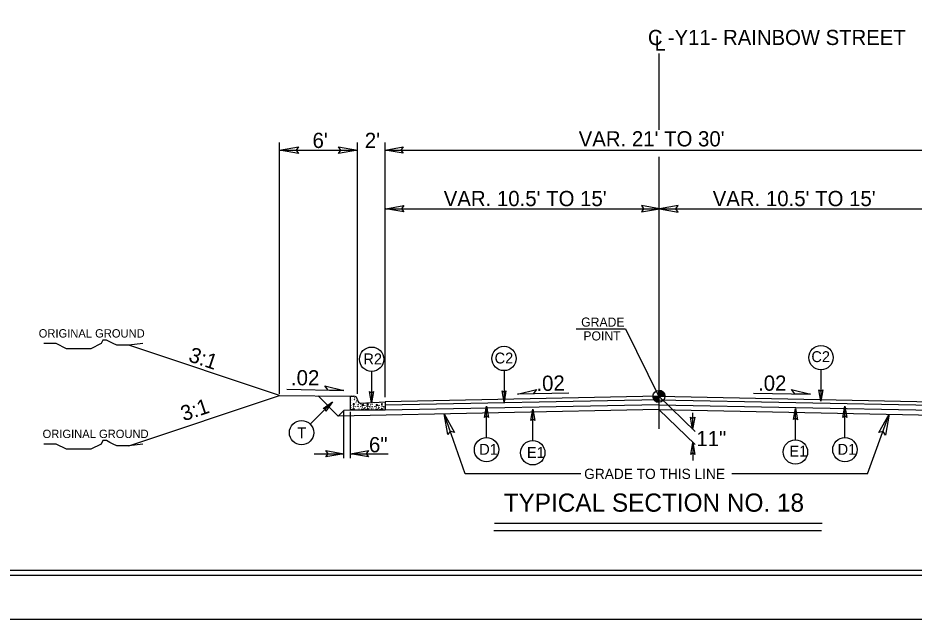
# Model space of a CAD drawing. Extents: x 957297 to 961629, y 830661 to 840840.
# Drawn here: x 959109.5 to 959568.3, y 831969.8 to 832277.6 of the extents above; entities that cross this region are included whole.
import ezdxf

# ---------------------------------------------------------------- set-up
doc = ezdxf.new("R2010")
doc.units = 0
for name, color, linetype in [('Default', 7, 'Continuous'), ('Old_Level_1', 7, 'Continuous'), ('Old_Level_11', 7, 'Continuous'), ('Old_Level_21', 7, 'Continuous'), ('Old_Level_3', 7, 'Continuous'), ('Prop Dimension Text', 7, 'Continuous'), ('Sheet Plot Border Inside CELL', 7, 'Continuous'), ('Sheet Plot Border Outside CELL', 7, 'Continuous'), ('Sheet Typical CELL', 7, 'Continuous'), ('Typical ID Circle CELL', 7, 'Continuous'), ('Typical Terminator CELL', 7, 'Continuous'), ('Typical Text Grade Point CELL', 7, 'Continuous'), ('Typical Text ID Circle CELL', 7, 'Continuous')]:
    doc.layers.add(name, color=color, linetype=linetype)

msp = doc.modelspace()

# ---------------------------------------------------------------- linework, layer by layer
at = {"layer": 'Default'}
for p, q in [((959437.72, 832259.33), (959437.72, 832220.36)), ((959437.72, 832206.44), (959437.72, 832067.17))]:
    msp.add_line(p, q, dxfattribs=at)
at = {"layer": 'Old_Level_1'}
for p, q in [((959243.49, 832085.16), (959243.49, 832213.72)), ((959283.31, 832085.16), (959283.31, 832213.72)), ((959297.55, 832083.47), (959297.55, 832213.72)), ((959243.49, 832209.87), (959283.31, 832209.87)), ((959297.55, 832209.87), (959577.94, 832209.87)), ((959297.81, 832179.86), (959437.97, 832179.86)), ((959437.97, 832179.86), (959578.19, 832179.86)), ((959243.49, 832084.22), (959166.3, 832109.95)), ((959166.3, 832058.49), (959243.49, 832084.22)), ((959243.49, 832084.22), (959279.75, 832083.85)), ((959247.13, 832087.44), (959276.35, 832086.85)), ((959273.48, 832073.69), (959263.16, 832084.02)), ((959437.72, 832083.84), (959297.55, 832081.01)), ((959391.59, 832085.45), (959365.21, 832084.92)), ((959434.66, 832083.83), (959437.72, 832083.83)), ((959437.72, 832083.83), (959437.72, 832086.9)), ((959437.72, 832083.84), (959577.94, 832081.01)), ((959437.72, 832083.84), (959456.19, 832065.91)), ((959440.78, 832083.83), (959437.72, 832083.83)), ((959437.72, 832080.78), (959437.72, 832083.83)), ((959437.72, 832083.83), (959437.72, 832080.78)), ((959486.07, 832085.54), (959515.29, 832084.95)), ((959437.72, 832082.12), (959297.55, 832079.28)), ((959437.72, 832079.56), (959297.55, 832076.73)), ((959437.72, 832082.12), (959577.94, 832079.28)), ((959437.72, 832079.56), (959577.94, 832076.73)), ((959437.72, 832077.02), (959273.48, 832073.69)), ((959276.45, 832076.66), (959273.48, 832073.69)), ((959279.75, 832076.73), (959276.45, 832076.66)), ((959276.45, 832052.17), (959276.45, 832076.22)), ((959279.75, 832052.17), (959279.75, 832075.93)), ((959338.54, 832044.15), (959327.78, 832074.79)), ((959437.72, 832077.02), (959456.19, 832059.09)), ((959437.72, 832077.02), (959602.01, 832073.69)), ((959454.98, 832075.45), (959454.98, 832067.09)), ((959544.48, 832044.08), (959555.64, 832074.63)), ((959455.04, 832060.19), (959455.05, 832050.97)), ((959261.26, 832054.47), (959276.45, 832054.47)), ((959279.75, 832054.47), (959299.02, 832054.47)), ((959397.67, 832044.15), (959338.54, 832044.15)), ((959544.48, 832044.08), (959475.06, 832044.08)), ((959520.94, 832014.9), (959353.24, 832014.9)), ((959521.22, 832018.71), (959353.52, 832018.71))]:
    msp.add_line(p, q, dxfattribs=at)
for points in [[(959434.68, 832083.83), (959434.68, 832083.51)], [(959434.74, 832083.83), (959434.74, 832083.15)], [(959434.8, 832083.83), (959434.8, 832082.93)], [(959434.86, 832083.83), (959434.86, 832082.74)], [(959434.93, 832083.83), (959434.93, 832082.6)], [(959434.99, 832083.83), (959434.99, 832082.47)], [(959435.05, 832083.83), (959435.05, 832082.36)], [(959435.11, 832083.83), (959435.11, 832082.24)], [(959435.17, 832083.83), (959435.17, 832082.16)], [(959435.23, 832083.83), (959435.23, 832082.07)], [(959435.3, 832083.83), (959435.3, 832081.98)], [(959435.36, 832083.83), (959435.36, 832081.91)], [(959435.42, 832083.83), (959435.42, 832081.84)], [(959435.47, 832083.83), (959435.47, 832081.76)], [(959435.53, 832083.83), (959435.53, 832081.7)], [(959435.6, 832083.83), (959435.6, 832081.64)], [(959435.66, 832083.83), (959435.66, 832081.59)], [(959435.72, 832083.83), (959435.72, 832081.53)], [(959435.78, 832083.83), (959435.78, 832081.48)], [(959435.85, 832083.83), (959435.85, 832081.42)], [(959435.9, 832083.83), (959435.9, 832081.38)], [(959435.96, 832083.83), (959435.96, 832081.34)], [(959436.02, 832083.83), (959436.02, 832081.3)], [(959436.09, 832083.83), (959436.09, 832081.25)], [(959436.15, 832083.83), (959436.15, 832081.21)], [(959436.21, 832083.83), (959436.21, 832081.17)], [(959436.28, 832083.83), (959436.28, 832081.14)], [(959436.33, 832083.83), (959436.33, 832081.13)], [(959436.39, 832083.83), (959436.39, 832081.09)], [(959436.46, 832083.83), (959436.46, 832081.05)], [(959436.52, 832083.83), (959436.52, 832081.03)], [(959436.58, 832083.83), (959436.58, 832081)], [(959436.64, 832083.83), (959436.64, 832080.98)], [(959436.7, 832083.83), (959436.7, 832080.96)], [(959436.75, 832083.83), (959436.75, 832080.94)], [(959436.82, 832083.83), (959436.82, 832080.92)], [(959436.88, 832083.83), (959436.88, 832080.9)], [(959436.94, 832083.83), (959436.94, 832080.88)], [(959437, 832083.83), (959437, 832080.88)], [(959437.07, 832083.83), (959437.07, 832080.85)], [(959437.13, 832083.83), (959437.13, 832080.84)], [(959437.19, 832083.83), (959437.19, 832080.84)], [(959437.25, 832083.83), (959437.25, 832080.82)], [(959437.31, 832083.83), (959437.31, 832080.8)], [(959437.38, 832083.83), (959437.38, 832080.8)], [(959437.44, 832083.83), (959437.44, 832080.8)], [(959437.5, 832083.83), (959437.5, 832080.78)], [(959437.56, 832083.83), (959437.56, 832080.78)], [(959437.61, 832083.83), (959437.61, 832080.78)], [(959437.67, 832083.83), (959437.67, 832080.78), (959437.67, 832080.78)], [(959437.76, 832086.9), (959437.76, 832086.9), (959437.76, 832083.83)], [(959437.81, 832086.9), (959437.81, 832083.83)], [(959437.87, 832086.89), (959437.87, 832083.83)], [(959437.94, 832086.88), (959437.94, 832083.83)], [(959438, 832086.88), (959438, 832083.83)], [(959438.06, 832086.88), (959438.06, 832083.83)], [(959438.12, 832086.87), (959438.12, 832083.83)], [(959438.18, 832086.87), (959438.18, 832083.83)], [(959438.23, 832086.84), (959438.23, 832083.83)], [(959438.3, 832086.84), (959438.3, 832083.83)], [(959438.36, 832086.83), (959438.36, 832083.83)], [(959438.42, 832086.81), (959438.42, 832083.83)], [(959438.49, 832086.79), (959438.49, 832083.83)], [(959438.55, 832086.78), (959438.55, 832083.83)], [(959438.61, 832086.76), (959438.61, 832083.83)], [(959438.67, 832086.74), (959438.67, 832083.83)], [(959438.74, 832086.72), (959438.73, 832083.83)], [(959438.79, 832086.7), (959438.79, 832083.83)], [(959438.85, 832086.69), (959438.85, 832083.83)], [(959438.92, 832086.66), (959438.92, 832083.83)], [(959438.98, 832086.63), (959438.98, 832083.83)], [(959439.04, 832086.59), (959439.04, 832083.83)], [(959439.09, 832086.57), (959439.09, 832083.83)], [(959439.15, 832086.55), (959439.15, 832083.83)], [(959439.21, 832086.51), (959439.21, 832083.83)], [(959439.28, 832086.47), (959439.28, 832083.83)], [(959439.34, 832086.43), (959439.34, 832083.83)], [(959439.4, 832086.39), (959439.4, 832083.83)], [(959439.47, 832086.34), (959439.47, 832083.83)], [(959439.52, 832086.31), (959439.52, 832083.83)], [(959439.59, 832086.26), (959439.59, 832083.83)], [(959439.65, 832086.21), (959439.65, 832083.83)], [(959439.71, 832086.17), (959439.71, 832083.83)], [(959439.77, 832086.11), (959439.77, 832083.83)], [(959439.83, 832086.05), (959439.83, 832083.83)], [(959439.9, 832085.99), (959439.9, 832083.83)], [(959439.95, 832085.93), (959439.95, 832083.83)], [(959440.01, 832085.87), (959440.01, 832083.83)], [(959440.07, 832085.8), (959440.07, 832083.83)], [(959440.13, 832085.71), (959440.13, 832083.83)], [(959440.2, 832085.63), (959440.2, 832083.83)], [(959440.26, 832085.55), (959440.26, 832083.83)], [(959440.32, 832085.46), (959440.32, 832083.83)], [(959440.38, 832085.35), (959440.38, 832083.83)], [(959440.44, 832085.24), (959440.44, 832083.83)], [(959440.5, 832085.1), (959440.5, 832083.83)], [(959440.57, 832084.95), (959440.57, 832083.83)], [(959440.63, 832084.79), (959440.63, 832083.83)], [(959440.69, 832084.58), (959440.69, 832083.83)], [(959440.75, 832084.28), (959440.75, 832083.83)]]:
    msp.add_lwpolyline(points, dxfattribs=at)
msp.add_circle((959437.72, 832083.84), 3.06, dxfattribs=at)
for start, end in [(179.9905, 269.9905), (359.9905, 89.9905)]:
    msp.add_arc((959437.72, 832083.84), 3.06, start, end, dxfattribs=at)
at = {"layer": 'Old_Level_11'}
for p, q in [((959268.34, 832087.01), (959266.61, 832089.27)), ((959266.61, 832089.27), (959276.35, 832086.85)), ((959276.35, 832086.85), (959268.34, 832087.01)), ((959365.21, 832084.92), (959374.96, 832087.34)), ((959373.23, 832085.08), (959365.21, 832084.92)), ((959374.96, 832087.34), (959373.23, 832085.08)), ((959507.28, 832085.11), (959505.55, 832087.37)), ((959505.55, 832087.37), (959515.29, 832084.95)), ((959515.29, 832084.95), (959507.28, 832085.11))]:
    msp.add_line(p, q, dxfattribs=at)
for points in [[(959253.1, 832208.22), (959243.49, 832209.87), (959253.15, 832211.58), (959251.93, 832209.87)], [(959273.71, 832211.53), (959283.31, 832209.87), (959273.65, 832208.16), (959274.88, 832209.87)], [(959447.58, 832181.51), (959437.97, 832179.86), (959447.64, 832178.14), (959446.41, 832179.86)], [(959329.55, 832064.21), (959327.78, 832074.79), (959333.06, 832065.38), (959330.85, 832066.04)], [(959550.3, 832065.33), (959555.64, 832074.63), (959553.76, 832064.01), (959552.46, 832065.91)]]:
    msp.add_lwpolyline(points, close=True, dxfattribs=at)
at = {"layer": 'Old_Level_21'}
for points in [[(959173.4, 832110.83), (959166.3, 832109.95), (959164.53, 832109.95), (959161.87, 832109.95), (959160.09, 832109.95), (959158.32, 832110.83), (959156.54, 832111.73), (959154.77, 832112.61), (959153, 832112.61), (959152.1, 832110.83), (959150.34, 832109.95), (959148.56, 832109.05), (959146.79, 832108.18), (959145.02, 832108.18), (959143.25, 832108.18), (959141.47, 832108.18), (959139.7, 832108.18), (959137.92, 832108.18), (959136.15, 832108.18), (959134.38, 832108.18), (959132.61, 832109.05), (959130.84, 832109.95), (959129.07, 832110.83), (959126.39, 832110.83), (959124.62, 832110.83), (959122.85, 832110.83)], [(959173.4, 832059.37), (959166.3, 832058.49), (959164.53, 832058.49), (959161.87, 832058.49), (959160.09, 832058.49), (959158.32, 832059.37), (959156.54, 832060.26), (959154.77, 832061.14), (959153, 832061.14), (959152.1, 832059.37), (959150.34, 832058.49), (959148.56, 832057.59), (959146.79, 832056.72), (959145.02, 832056.72), (959143.25, 832056.72), (959141.47, 832056.72), (959139.7, 832056.72), (959137.92, 832056.72), (959136.15, 832056.72), (959134.38, 832056.72), (959132.61, 832057.59), (959130.84, 832058.49), (959129.07, 832059.37), (959126.39, 832059.37), (959124.62, 832059.37), (959122.85, 832059.37)]]:
    msp.add_lwpolyline(points, dxfattribs=at)
at = {"layer": 'Old_Level_3'}
for p, q in [((959279.75, 832080.29), (959279.75, 832083.55)), ((959280.06, 832083.85), (959281.54, 832083.85)), ((959279.75, 832076.73), (959279.75, 832080.29)), ((959281.12, 832080.04), (959281.12, 832079.42)), ((959281.75, 832080.01), (959281.12, 832080.04)), ((959281.12, 832079.42), (959281.75, 832080.01)), ((959283.46, 832081.66), (959283.34, 832081.5)), ((959283.34, 832081.5), (959283.5, 832081.54)), ((959285.16, 832080.39), (959297.55, 832081.01)), ((959285.16, 832080.39), (959285.16, 832080.39)), ((959285.65, 832079.61), (959285.75, 832079.09)), ((959286.54, 832079.36), (959285.65, 832079.61)), ((959285.75, 832079.09), (959286.54, 832079.36)), ((959288.35, 832080.04), (959288.35, 832079.42)), ((959288.98, 832080.01), (959288.35, 832080.04)), ((959288.35, 832079.42), (959288.98, 832080.01)), ((959292.88, 832079.61), (959292.98, 832079.09)), ((959293.77, 832079.36), (959292.88, 832079.61)), ((959292.98, 832079.09), (959293.77, 832079.36)), ((959295.58, 832080.04), (959295.58, 832079.42)), ((959296.2, 832080.01), (959295.58, 832080.04)), ((959295.58, 832079.42), (959296.2, 832080.01)), ((959297.55, 832081.01), (959297.55, 832076.73)), ((959297.55, 832076.73), (959279.75, 832076.73)), ((959281.03, 832077.14), (959281.53, 832077.84)), ((959281.71, 832077.18), (959281.03, 832077.14)), ((959281.53, 832077.84), (959281.71, 832077.18)), ((959285.45, 832076.85), (959285.81, 832077.51)), ((959286.41, 832077.08), (959285.45, 832076.85)), ((959285.81, 832077.51), (959286.41, 832077.08)), ((959288.26, 832077.14), (959288.75, 832077.84)), ((959288.94, 832077.18), (959288.26, 832077.14)), ((959288.75, 832077.84), (959288.94, 832077.18)), ((959292.68, 832076.85), (959293.04, 832077.51)), ((959293.64, 832077.08), (959292.68, 832076.85)), ((959293.04, 832077.51), (959293.64, 832077.08)), ((959295.48, 832077.14), (959295.98, 832077.84)), ((959296.17, 832077.18), (959295.48, 832077.14)), ((959295.98, 832077.84), (959296.17, 832077.18))]:
    msp.add_line(p, q, dxfattribs=at)
for centre in [(959281.72, 832083.08), (959279.81, 832081.99), (959279.91, 832079.22), (959280.5, 832080.51), (959280.63, 832081.9), (959280.66, 832078.79), (959280.8, 832082.69), (959281.49, 832078.89), (959281.89, 832082.09), (959282.35, 832078.52), (959282.58, 832080.71), (959282.88, 832079.52), (959282.91, 832082.95), (959282.94, 832081.56), (959283.54, 832078.43), (959283.64, 832078.72), (959283.67, 832079.58), (959283.77, 832080.67), (959284.83, 832080.01), (959285.12, 832078.56), (959286.38, 832079.85), (959287.14, 832079.22), (959287.89, 832078.79), (959288.72, 832078.89), (959289.58, 832078.52), (959290.11, 832079.52), (959290.77, 832078.43), (959290.86, 832078.72), (959290.9, 832079.58), (959292.05, 832080.01), (959292.35, 832078.56), (959293.61, 832079.85), (959294.37, 832079.22), (959294.95, 832080.51), (959295.12, 832078.79), (959295.94, 832078.89), (959296.8, 832078.52), (959297.03, 832080.71), (959297.33, 832079.52), (959279.95, 832076.88), (959280.04, 832078.07), (959280.5, 832077.14), (959281.23, 832078.3), (959282.51, 832077.94), (959283.37, 832077.44), (959284.1, 832077.61), (959285.82, 832078.27), (959286.84, 832077.71), (959286.94, 832078.27), (959287.17, 832076.88), (959287.26, 832078.07), (959287.73, 832077.14), (959288.45, 832078.3), (959289.74, 832077.94), (959290.6, 832077.44), (959291.33, 832077.61), (959293.05, 832078.27), (959294.07, 832077.71), (959294.17, 832078.27), (959294.4, 832076.88), (959294.49, 832078.07), (959294.95, 832077.14), (959295.68, 832078.3), (959296.97, 832077.94)]:
    msp.add_circle(centre, 0.0464, dxfattribs=at)
for centre, radius, start, end in [((959280.06, 832083.55), 0.309, 90, 180), ((959279.95, 832083.78), 0.0464, 259.6531, 10.3469), ((959281.54, 832082.08), 1.78, 1.0734, 90), ((959285.07, 832082.14), 1.76, 181.0734, 272.8624), ((959287.73, 832080.51), 0.0464, 167.7795, 17.938), ((959291, 832080.67), 0.0464, 169.8374, 15.8801), ((959279.71, 832078.27), 0.0464, 330.4173, 29.5827)]:
    msp.add_arc(centre, radius, start, end, dxfattribs=at)
at = {"layer": 'Sheet Plot Border Inside CELL'}
msp.add_lwpolyline([(960390.3, 833047.34), (958723.8, 833047.34), (958723.8, 831992.24), (960390.3, 831992.24)], close=True, dxfattribs=at)
at = {"layer": 'Sheet Plot Border Outside CELL'}
msp.add_lwpolyline([(960394.8, 833069.79), (958710.8, 833069.79), (958710.8, 831969.79), (960394.8, 831969.79)], close=True, dxfattribs=at)
at = {"layer": 'Sheet Typical CELL'}
msp.add_lwpolyline([(960377.8, 833044.79), (958877.8, 833044.79), (958877.8, 831994.79), (960377.8, 831994.79)], close=True, dxfattribs=at)
at = {"layer": 'Typical ID Circle CELL'}
for p, q in [((959358.39, 832096.98), (959358.39, 832080.9)), ((959520.68, 832097.44), (959520.68, 832081.35)), ((959290.59, 832096.61), (959290.59, 832080.52)), ((959259.12, 832069.61), (959270.49, 832080.98)), ((959349.43, 832062.76), (959349.43, 832078.85)), ((959532.93, 832062.76), (959532.93, 832078.85)), ((959373.11, 832061.17), (959373.11, 832077.26)), ((959507.59, 832061.57), (959507.59, 832077.66))]:
    msp.add_line(p, q, dxfattribs=at)
for centre in [(959290.59, 832102.84), (959358.39, 832103.21), (959520.68, 832103.67), (959254.72, 832065.2), (959349.43, 832056.54), (959373.11, 832054.95), (959507.59, 832055.35), (959532.93, 832056.54)]:
    msp.add_circle(centre, 6.23, dxfattribs=at)
at = {"layer": 'Typical Terminator CELL'}
for points in [[(959306.72, 832208.28), (959297.5, 832209.87), (959306.77, 832211.51), (959305.59, 832209.87)], [(959307.03, 832178.27), (959297.81, 832179.86), (959307.08, 832181.5), (959305.9, 832179.86)], [(959428.75, 832178.27), (959437.97, 832179.86), (959428.7, 832181.5), (959429.88, 832179.86)], [(959291.58, 832086.29), (959290.59, 832080.52), (959289.56, 832086.32), (959290.59, 832085.58)], [(959359.39, 832086.66), (959358.39, 832080.9), (959357.37, 832086.69), (959358.39, 832085.96)], [(959521.67, 832087.12), (959520.68, 832081.35), (959519.66, 832087.15), (959520.68, 832086.41)], [(959265.72, 832077.61), (959270.49, 832080.98), (959267.12, 832076.16), (959266.92, 832077.4)], [(959348.44, 832073.08), (959349.43, 832078.85), (959350.45, 832073.05), (959349.43, 832073.79)], [(959531.94, 832073.08), (959532.93, 832078.85), (959533.95, 832073.05), (959532.93, 832073.79)], [(959372.12, 832071.49), (959373.11, 832077.26), (959374.13, 832071.46), (959373.11, 832072.2)], [(959506.6, 832071.9), (959507.59, 832077.66), (959508.62, 832071.86), (959507.59, 832072.6)], [(959456.02, 832073.16), (959454.98, 832067.09), (959453.9, 832073.19), (959454.98, 832072.41)], [(959454, 832054.13), (959455.04, 832060.19), (959456.12, 832054.09), (959455.04, 832054.87)], [(959267.23, 832056.06), (959276.45, 832054.47), (959267.18, 832052.83), (959268.36, 832054.47)], [(959288.97, 832052.88), (959279.75, 832054.47), (959289.03, 832056.11), (959287.85, 832054.47)]]:
    msp.add_lwpolyline(points, close=True, dxfattribs=at)
at = {"layer": 'Typical Text Grade Point CELL'}
for p, q in [((959395.28, 832118.39), (959420.61, 832118.39)), ((959420.61, 832118.39), (959437.72, 832083.83))]:
    msp.add_line(p, q, dxfattribs=at)

# ---------------------------------------------------------------- texts
at = {"layer": 'Old_Level_1'}
for s, height, p in [("VAR. 21' TO 30'", 7.8009, (959396.61, 832211.8)), ("VAR. 10.5' TO 15'", 7.8009, (959327.52, 832181.21)), ("VAR. 10.5' TO 15'", 7.8009, (959465.25, 832181.21)), ('GRADE TO THIS LINE', 5.2473, (959399.43, 832041.52)), ('TYPICAL SECTION NO. 18', 9.3239, (959358.19, 832024.75))]:
    msp.add_text(s, height=height, dxfattribs=at).set_placement(p)
at = {"layer": 'Old_Level_11'}
for s, height, p in [('GRADE', 4.671, (959397.89, 832119.51)), ('POINT', 4.671, (959399.02, 832112.44)), ('11"', 7.801, (959456.86, 832058.32))]:
    msp.add_text(s, height=height, dxfattribs=at).set_placement(p)
at = {"layer": 'Old_Level_21'}
for p in [(959120.14, 832113.94), (959122.13, 832062.48)]:
    msp.add_text('ORIGINAL GROUND', height=4.2722, dxfattribs=at).set_placement(p)
at = {"layer": 'Old_Level_3'}
for s, p in [("6'", (959260.34, 832210.99)), ("2'", (959287.11, 832210.99))]:
    msp.add_text(s, height=7.801, dxfattribs=at).set_placement(p)
for s, rotation, p in [('3:1', 341.5652, (959196.34, 832101.91)), ('.02', 359.4336, (959249.27, 832089.53)), ('3:1', 18.4348, (959194.37, 832071))]:
    msp.add_text(s, height=7.801, rotation=rotation, dxfattribs=at).set_placement(p)
at = {"layer": 'Prop Dimension Text'}
for s, height, rotation, p in [('C', 7.77, 0, (959432.07, 832263.7)), ('-Y11- RAINBOW STREET', 7.7675, 0, (959442.27, 832263.72)), ('L', 7.77, 0, (959435.46, 832260.77)), ('.02', 7.801, 1.1839, (959375.07, 832086.5)), ('.02', 7.801, 360, (959488.47, 832086.7)), ('6"', 7.801, 0, (959289.25, 832055.18))]:
    msp.add_text(s, height=height, rotation=rotation, dxfattribs=at).set_placement(p)
at = {"layer": 'Typical Text ID Circle CELL'}
for s, p in [('C2', (959353.58, 832100.66)), ('C2', (959515.77, 832101.37)), ('R2', (959286.39, 832100.21)), ('D1', (959345.7, 832053.92)), ('E1', (959370.14, 832052.32)), ('D1', (959529.2, 832053.92))]:
    msp.add_text(s, height=5.572, dxfattribs=at).set_placement(p)
for s, height, p in [('T', 5.57, (959252.54, 832062.33)), ('E1', 5.572, (959504.52, 832053.01))]:
    msp.add_text(s, height=height, rotation=360, dxfattribs=at).set_placement(p)

doc.saveas('drawing.dxf')
